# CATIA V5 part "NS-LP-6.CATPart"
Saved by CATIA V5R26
Part number: NS-LP-6
Bounding box of the stored display mesh (mm): x -3.967 to 61, y -43 to 7, z -4 to 4
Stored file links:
  Y:\業務部\坪井宗男\KHI\KHI治工具標準部品\Lピン\CATIAデータ\NS-LP-6.CATPart
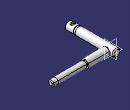
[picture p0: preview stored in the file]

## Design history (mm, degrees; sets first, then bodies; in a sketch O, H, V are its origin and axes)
Body1 (main body)
  Solid1: solid without history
